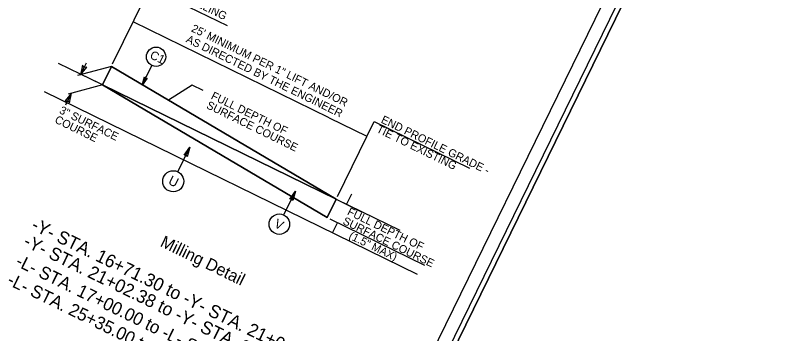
# Model space of a CAD drawing. Extents: x 1518247 to 1523638, y 635234 to 639927.
# Drawn here: x 1522205 to 1522921, y 638577 to 638875 of the extents above; entities that cross this region are included whole.
import ezdxf

# ---------------------------------------------------------------- set-up
doc = ezdxf.new("R2010")
doc.units = 0
for name, color, linetype in [('Default', 7, 'Continuous'), ('Old_Level_1', 7, 'Continuous'), ('Old_Level_11', 7, 'Continuous'), ('Prop Shade Light', 7, 'Continuous'), ('Sheet Plot Border Inside CELL', 7, 'Continuous'), ('Sheet Plot Border Outside CELL', 7, 'Continuous'), ('Sheet Typical CELL', 7, 'Continuous'), ('Typical ID Circle CELL', 7, 'Continuous'), ('Typical Pavement Slope CELL', 7, 'Continuous'), ('Typical Text ID Circle CELL', 7, 'Continuous')]:
    doc.layers.add(name, color=color, linetype=linetype)

# ---------------------------------------------------------------- blocks, each defined once
blk = doc.blocks.new('TERMINATOR')
at = {"layer": 'Prop Shade Light'}
blk.add_lwpolyline([(-0.469, 0.081), (0, 0), (-0.471, -0.083), (-0.411, 0)], close=True, dxfattribs=at)

msp = doc.modelspace()

# ---------------------------------------------------------------- linework, layer by layer
at = {"layer": 'Default'}
for p, q in [((1522265.96, 638819.2), (1522271.55, 638830.64)), ((1522286.58, 638809.83), (1522245.41, 638829.97)), ((1522295.06, 638827), (1522263.32, 638818.49)), ((1522286.58, 638809.83), (1522295, 638827.05)), ((1522505.59, 638702.72), (1522295, 638827.05)), ((1522284.18, 638811), (1522265.48, 638820.15)), ((1522286.58, 638809.83), (1522254.36, 638801.19)), ((1522497.17, 638685.5), (1522286.58, 638809.83)), ((1522505.59, 638702.72), (1522286.58, 638809.83)), ((1522370.62, 638809.64), (1522348.46, 638795.49)), ((1522380.92, 638804.6), (1522370.62, 638809.64)), ((1522581.7, 638632.32), (1522232.32, 638803.2)), ((1522252.22, 638791.12), (1522257.57, 638802.05)), ((1522505.59, 638702.72), (1522497.17, 638685.5)), ((1522505.59, 638702.72), (1522565.16, 638673.58)), ((1522507.99, 638701.54), (1522529.47, 638691.04))]:
    msp.add_line(p, q, dxfattribs=at)
for points in [[(1522438.02, 638198.63), (1520925.25, 638938.49), (1521408.53, 639926.64), (1522921.3, 639186.78)], [(1522286.58, 638809.83), (1522295, 638827.05), (1522505.59, 638702.72)]]:
    msp.add_lwpolyline(points, close=True, dxfattribs=at)
msp.add_lwpolyline([(1522286.58, 638809.83), (1522497.17, 638685.5), (1522505.59, 638702.72), (1522286.58, 638809.83)], dxfattribs=at)
at = {"layer": 'Old_Level_1'}
for p, q in [((1522296.18, 638829.45), (1522331.05, 638900.74)), ((1522331.05, 638900.74), (1522403.46, 638865.33)), ((1522499.06, 638778.95), (1522315.41, 638868.77)), ((1522499.06, 638778.95), (1522534.42, 638761.66)), ((1522506.76, 638705.12), (1522541.2, 638775.53)), ((1522541.2, 638775.53), (1522630.46, 638731.88)), ((1522520.02, 638707.57), (1522515.32, 638697.96)), ((1522499.57, 638684.32), (1522588.29, 638640.93)), ((1522502.2, 638671.12), (1522506.9, 638680.74))]:
    msp.add_line(p, q, dxfattribs=at)
at = {"layer": 'Old_Level_11'}
msp.add_line((1522357.29, 638728.44), (1522368.53, 638751.41), dxfattribs=at)
msp.add_lwpolyline([(1522363.08, 638743.87), (1522368.53, 638751.41), (1522365.94, 638742.42), (1522364.99, 638744.18)], close=True, dxfattribs=at)
msp.add_circle((1522352.95, 638719.55), 9.9, dxfattribs=at)
at = {"layer": 'Prop Shade Light'}
for p, q in [((1522295, 638827.05), (1522286.58, 638809.83)), ((1522286.58, 638809.83), (1522505.59, 638702.72))]:
    msp.add_line(p, q, dxfattribs=at)
msp.add_lwpolyline([(1522505.59, 638702.72), (1522348.46, 638795.49), (1522295, 638827.05)], dxfattribs=at)
for points in [[(1522328.58, 638816.22), (1522323.71, 638809.51), (1522326.03, 638817.52), (1522326.87, 638815.94)], [(1522462.2, 638702.9), (1522467.48, 638710.2), (1522464.97, 638701.49), (1522464.05, 638703.2)]]:
    msp.add_lwpolyline(points, close=True, dxfattribs=at)
at = {"layer": 'Sheet Plot Border Inside CELL'}
msp.add_lwpolyline([(1522907.39, 639168.59), (1521410.35, 639900.76), (1520946.79, 638952.95), (1522443.84, 638220.77)], close=True, dxfattribs=at)
at = {"layer": 'Sheet Plot Border Outside CELL'}
msp.add_lwpolyline([(1522921.3, 639186.78), (1521408.53, 639926.64), (1520925.25, 638938.49), (1522438.02, 638198.63)], close=True, dxfattribs=at)
at = {"layer": 'Sheet Typical CELL'}
msp.add_lwpolyline([(1522895.04, 639171.79), (1521547.57, 639830.81), (1521086.25, 638887.58), (1522433.73, 638228.56)], close=True, dxfattribs=at)
at = {"layer": 'Typical ID Circle CELL'}
for p, q in [((1522323.71, 638809.51), (1522332.86, 638828.1)), ((1522456.58, 638687.95), (1522467.48, 638710.2))]:
    msp.add_line(p, q, dxfattribs=at)
for centre, radius in [((1522336.86, 638836.18), 9.02), ((1522452.36, 638679.34), 9.59)]:
    msp.add_circle(centre, radius, dxfattribs=at)

# ---------------------------------------------------------------- block references
at = {"layer": 'Default', "xscale": 19.088016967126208, "yscale": -27.397260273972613}
for p, rotation in [((1522265.96, 638819.2), -116.06227537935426), ((1522257.57, 638802.05), 63.93772462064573)]:
    msp.add_blockref('TERMINATOR', p, dxfattribs=dict(at, rotation=rotation))

# ---------------------------------------------------------------- texts
at = {"layer": 'Default'}
for s, rotation, p in [('BEGIN MILLING', 333.9378, (1522334.32, 638902.85)), ('FULL DEPTH OF', 333.93772, (1522387.71, 638797.1)), ('3" SURFACE', 333.93772, (1522245.56, 638783.63)), ('SURFACE COURSE ', 333.93772, (1522383.39, 638788.27)), ('COURSE', 333.93772, (1522241.24, 638774.8)), ('FULL DEPTH OF', 333.9378, (1522515.41, 638688.64)), ('SURFACE COURSE', 333.9378, (1522511.09, 638679.81)), ('    (1.5" MAX)', 333.9378, (1522506.77, 638670.97))]:
    msp.add_text(s, height=7.5, rotation=rotation, dxfattribs=at).set_placement(p)
at = {"layer": 'Old_Level_1'}
for s, height, rotation, p in [('25\' MINIMUM PER 1" LIFT AND/OR ', 7.5, 333.93771, (1522369.2, 638860.24)), ('AS DIRECTED BY THE ENGINEER', 7.5, 333.93771, (1522364.25, 638850.13)), ('END PROFILE GRADE - ', 7.5, 333.9378, (1522547.02, 638774.77)), ('TIE TO EXISTING', 7.5, 333.9378, (1522542.7, 638765.94)), ('Milling Detail', 11.2828, 333.93772, (1522339.85, 638659.01))]:
    msp.add_text(s, height=height, rotation=rotation, dxfattribs=at).set_placement(p)
at = {"layer": 'Typical Pavement Slope CELL'}
for s, height, rotation, p in [('-Y- STA. 16+71.30 to -Y- STA. 21+02.38', 12.1642, 334.0511, (1522219.07, 638674.79)), ('-Y- STA. 21+02.38 to -Y- STA. 21+59.64', 12.1642, 334.0511, (1522211.61, 638659.45)), ('-L- STA. 17+00.00 to -L- STA. 17+50.00', 11.8983, 333.89618, (1522204.3, 638640.89)), ('-L- STA. 25+35.00 to -L- STA. 25+85.00', 11.8983, 333.89618, (1522196.49, 638623.31))]:
    msp.add_text(s, height=height, rotation=rotation, dxfattribs=at).set_placement(p)
at = {"layer": 'Typical Text ID Circle CELL'}
for s, height, rotation, p in [('C1', 8.07, 333.93772, (1522330.32, 638835.14)), ('U', 8.86, 333.93772, (1522347.53, 638717.26)), ('V', 8.58, 333.89618, (1522446.84, 638677))]:
    msp.add_text(s, height=height, rotation=rotation, dxfattribs=at).set_placement(p)

doc.saveas('drawing.dxf')
